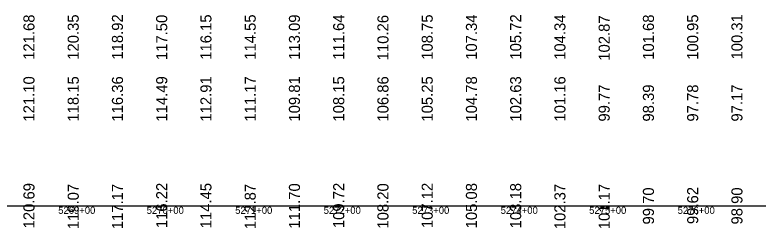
# Model space of a CAD drawing. Extents: x 2147288 to 2220488, y 740833 to 759333.
# Drawn here: x 2209208 to 2210048, y 750058 to 750299 of the extents above; entities that cross this region are included whole.
import ezdxf

# ---------------------------------------------------------------- set-up
doc = ezdxf.new("R2010")
doc.units = 0
for name, color, linetype in [('RD_DDB_Profile_EX', 7, 'Continuous'), ('RD_DDB_StaTX', 7, 'Continuous'), ('RD_DDB_StripGrade', 7, 'Continuous'), ('RD_GPK_Profile_Cell', 7, 'Continuous')]:
    doc.layers.add(name, color=color, linetype=linetype)

msp = doc.modelspace()

# ---------------------------------------------------------------- linework, layer by layer
at = {"layer": 'RD_GPK_Profile_Cell'}
msp.add_line((2198888.28, 750083.43), (2220488.28, 750083.43), dxfattribs=at)

# ---------------------------------------------------------------- texts
at = {"layer": 'RD_DDB_Profile_EX'}
for s, p in [('121.68', (2209230.08, 750248.05)), ('120.35', (2209280.08, 750248.1)), ('118.92', (2209330.08, 750248.3)), ('117.50', (2209380.08, 750247.79)), ('116.15', (2209430.08, 750248.1)), ('114.55', (2209480.08, 750248.1)), ('113.09', (2209530.08, 750248.05)), ('111.64', (2209580.08, 750248.07)), ('110.26', (2209630.08, 750247.54)), ('108.75', (2209680.08, 750248.1)), ('107.34', (2209730.08, 750248.07)), ('105.72', (2209780.08, 750248.3)), ('104.34', (2209830.08, 750248.07)), ('102.87', (2209880.08, 750247.08)), ('101.68', (2209930.08, 750248.05)), ('100.95', (2209980.08, 750248.1)), ('100.31', (2210030.08, 750248.41)), ('120.69', (2209230.08, 750058.05)), ('119.07', (2209280.08, 750057.08)), ('117.17', (2209330.08, 750057.08)), ('116.22', (2209380.08, 750058.3)), ('114.45', (2209430.08, 750058.1)), ('112.87', (2209480.08, 750057.08)), ('111.70', (2209530.08, 750057.79)), ('109.72', (2209580.08, 750058.3)), ('108.20', (2209630.08, 750057.79)), ('107.12', (2209680.08, 750058.3)), ('105.08', (2209730.08, 750058.05)), ('103.18', (2209780.08, 750058.05)), ('102.37', (2209830.08, 750057.08)), ('101.17', (2209880.08, 750057.08)), ('99.70', (2209930.08, 750062.38)), ('99.62', (2209980.08, 750062.89)), ('98.90', (2210030.08, 750062.38))]:
    msp.add_text(s, height=12.5, rotation=90, dxfattribs=at).set_placement(p)
at = {"layer": 'RD_DDB_StaTX'}
for s, p in [('5269+00', (2209256.88, 750074.43)), ('5269+00', (2209256.88, 750074.43)), ('5269+00', (2209256.88, 750074.43)), ('5270+00', (2209356.88, 750074.43)), ('5270+00', (2209356.88, 750074.43)), ('5270+00', (2209356.88, 750074.43)), ('5271+00', (2209456.88, 750074.43)), ('5271+00', (2209456.88, 750074.43)), ('5271+00', (2209456.88, 750074.43)), ('5272+00', (2209556.88, 750074.43)), ('5272+00', (2209556.88, 750074.43)), ('5272+00', (2209556.88, 750074.43)), ('5273+00', (2209656.88, 750074.43)), ('5273+00', (2209656.88, 750074.43)), ('5273+00', (2209656.88, 750074.43)), ('5274+00', (2209756.88, 750074.43)), ('5274+00', (2209756.88, 750074.43)), ('5274+00', (2209756.88, 750074.43)), ('5275+00', (2209856.88, 750074.43)), ('5275+00', (2209856.88, 750074.43)), ('5275+00', (2209856.88, 750074.43)), ('5276+00', (2209956.88, 750074.43)), ('5276+00', (2209956.88, 750074.43)), ('5276+00', (2209956.88, 750074.43))]:
    msp.add_text(s, height=8, dxfattribs=at).set_placement(p)
at = {"layer": 'RD_DDB_StripGrade'}
for s, p in [('121.10', (2209230.08, 750178.43)), ('118.15', (2209280.08, 750178.43)), ('116.36', (2209330.08, 750178.43)), ('114.49', (2209380.08, 750178.43)), ('112.91', (2209430.08, 750178.43)), ('111.17', (2209480.08, 750178.43)), ('109.81', (2209530.08, 750178.43)), ('108.15', (2209580.08, 750178.43)), ('106.86', (2209630.08, 750178.43)), ('105.25', (2209680.08, 750178.43)), ('104.78', (2209730.08, 750178.43)), ('102.63', (2209780.08, 750178.43)), ('101.16', (2209830.08, 750178.43)), ('99.77', (2209880.08, 750178.43)), ('98.39', (2209930.08, 750178.43)), ('97.78', (2209980.08, 750178.43)), ('97.17', (2210030.08, 750178.43))]:
    msp.add_text(s, height=12.5, rotation=90, dxfattribs=at).set_placement(p)

doc.saveas('drawing.dxf')
